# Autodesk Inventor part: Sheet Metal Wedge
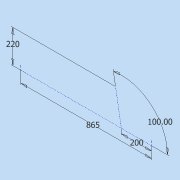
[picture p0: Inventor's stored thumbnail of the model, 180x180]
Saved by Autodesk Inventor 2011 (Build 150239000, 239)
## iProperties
Created: 2010-10
Part Number: Sheet Metal Wedge
Material: Default
Document SubType Name: Sheet Metal
Designer: jmather
Density: 1 g/cm^3
Sheet Metal Rule: Default_mm
Author: jmather
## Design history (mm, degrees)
sketch "Sketch1"
  geometry: L1 (-200, 0)-(665, 0); L2 (0, 0)-(38.792, 220)
  constraints: 4 end point, 1 horizontal, 1 point on line
  dimensions: "d3" = 865 distance of L1.start L1.end; "d4" = 200 distance of L2.start L1.start; "d15" = 100 deg angle of L1 L2; "d16" = 220 vertical distance of L1.end L2.end
workplane "Work Plane1"
sketch "Sketch2"
  geometry: L1 (0, 0)-(223.394, 0) reference; L2 (0, 0)-(223.394, -319.039); L3 (0, 0)-(223.394, 319.039); L4 (223.394, -319.039)-(223.394, 319.039)
  constraints: 6 end point, 1 midpoint, 1 perpendicular, 1 other
  dimensions: "d6" = 110 deg angle of L3 L2
feature "Stitch Surface1"
workplane "Work Plane2"
sketch "Sketch3"
  geometry: L1 (0, 0)-(-455.201, 0) reference; L2 (-455.201, 0)-(-223.607, -227.565); L3 (0, 0)-(-447.214, -455.131); L4 (0, 0)-(0, -218); L5 (-455.058, 0)-(-223.537, -227.494); L6 (-455.198, -0.143)-(-223.677, -227.637); L7 (-223.607, -227.565)-(-4.403, -442.957); L8 (-223.537, -227.494)-(-164.822, -285.188); L9 (0, 0)-(-455.058, 0); L10 (-447.214, -455.131)-(-229.248, -451.306); L11 (-447.214, -455.131)-(-455.198, -0.143); L12 (-164.962, -285.331)-(-455.198, -0.143); A1 r 225 centre (-4.403, -442.957) between (0, -218) and (-164.822, -285.188); A2 r 225 centre (-4.403, -442.957) between (-164.962, -285.331) and (-229.248, -451.306); 1 further point
  constraints: 22 end point, 4 perpendicular, 4 point on circle, 4 symmetric about line, 3 parallel, 3 point on line, 2 centre point, 1 coincident, 1 midpoint, 1 other
  dimensions: "d19" = 0.2 distance between parallel lines of L6 L5; "d20" = 218 distance of L1.start L4.end; "d21" = 225 radius of A1
workplane "Work Plane3"
sketch "Sketch4"
  geometry: L1 (-7.862, 0)-(-736.426, 0) reference; L2 (-736.426, 0)-(-604.436, 173.501) reference; L3 (-100, 0)-(-723.861, 0); L4 (-723.861, 0)-(-704.842, 25); L5 (-704.842, 25)-(-100, 25); L6 (-100, 0)-(-100, 25); 2 further points
  constraints: 8 end point, 2 parallel, 2 point on line, 1 perpendicular
  dimensions: "d27" = 25 distance of L3.start L5.end; "d29" = 10 distance between parallel lines of L2 L4; "d63" = 100 distance from line of L6 point (0, 0)
sketch "Sketch5"
  geometry: L1 (-736.426, 0)-(-604.436, 173.501) reference; L2 (-704.842, 25)-(-100, 25) reference; L3 (-613.518, 161.563)-(-593.621, 146.427); L4 (-593.621, 146.427)-(-685.235, 26); L5 (-685.235, 26)-(-716.646, 26); 1 further point
  constraints: 6 end point, 2 perpendicular, 2 point on line, 1 parallel
  dimensions: "d30" = 25 distance of L3.start L3.end (= d27); "d31" = 1 distance between parallel lines of L2 L5; "d32" = 15 distance from line of L3 L1.end
fillet "Fillet1" dims "d17" = 6 (= 2 x Thickness)
thicken "Thicken1" dims "d18" = 3 (= Thickness)
node "Face1"
node "Face4"
node "Face2"
node "Face3"
node "Flange1"
feature "Corner Chamfer1" dims "d55" = 19, "d56" = 6, angle "d57" = 45 deg
feature "Corner2" dims "d58" = 12 (= CornerReliefSize), "d59" = 3 (= BendRadius), "d60" = 0.2, "d61" = 0, "d62" = 10, "Thickness" = 3 (derived)
mirror "Mirror1"
body "Solid1"
body "Srf1"
body "Srf2"
body "Srf3"
face "Plate1" dims "d22" = 3 (= BendRadius), "d23" = 3 (= BendReliefWidth), "d25" = 6 (= MinimumRemnant), "Thickness" = 3 (derived)
bend "Bend1" dims "d22" = 3 (= BendRadius), "d23" = 3 (= BendReliefWidth), "d24" = 1.5 (= BendReliefDepth), "d25" = 6 (= MinimumRemnant), "d26" = 3 (= BendRadius), "SeamGap" = 0.01, "Thickness" = 3 (derived)
face "Plate2" dims "d33" = 3 (= BendRadius), "d34" = 3 (= BendReliefWidth), "d36" = 6 (= MinimumRemnant), "Thickness" = 3 (derived)
bend "Bend2" dims "d33" = 3 (= BendRadius), "d34" = 3 (= BendReliefWidth), "d35" = 1.5 (= BendReliefDepth), "d36" = 6 (= MinimumRemnant), "d37" = 3 (= BendRadius), "SeamGap" = 0.01, "Thickness" = 3 (derived)
face "Plate3" dims "d38" = 3 (= BendRadius), "d39" = 3 (= BendReliefWidth), "d41" = 6 (= MinimumRemnant), "Thickness" = 3 (derived)
bend "Bend3" dims "d38" = 3 (= BendRadius), "d39" = 3 (= BendReliefWidth), "d40" = 1.5 (= BendReliefDepth), "d41" = 6 (= MinimumRemnant), "d42" = 3 (= BendRadius), "SeamGap" = 0.01, "Thickness" = 3 (derived)
sketch "Sketch6"
  geometry: L1 (-270.377, -249.1)-(-16.18, -14.907); L2 (-16.18, -14.907)-(-33.119, 3.48); L3 (-33.119, 3.48)-(-287.317, -230.713); L4 (-287.317, -230.713)-(-270.377, -249.1)
  constraints: 8 end point
face "Plate4" dims "d43" = 3 (= BendReliefWidth), "d44" = 1.5 (= BendReliefDepth), "d45" = 6 (= MinimumRemnant), "d46" = 3 (= BendRadius), "d47" = 22, "d48" = 22, "d49" = 25, "d50" = 90 deg, "d51" = 3 (= BendRadius), "d52" = 12 (= CornerReliefSize), "d53" = 3 (= GapSize), "d54" = 3 (= JacobiRadiusSize), "SeamGap" = 0.01, "Thickness" = 3 (derived)
bend "Bend4" dims "d43" = 3 (= BendReliefWidth), "d44" = 1.5 (= BendReliefDepth), "d45" = 6 (= MinimumRemnant), "d46" = 3 (= BendRadius), "d49" = 25, "d50" = 90 deg, "d51" = 3 (= BendRadius), "SeamGap" = 0.01, "Thickness" = 3 (derived)
feature "Corner1" dims "d49" = 25, "d50" = 90 deg, "d52" = 12 (= CornerReliefSize), "d53" = 3 (= GapSize), "d54" = 3 (= JacobiRadiusSize)
face "Plate5" dims "d64" = 3 (= BendRadius), "d65" = 3 (= BendReliefWidth), "d67" = 6 (= MinimumRemnant), "Thickness" = 3 (derived)
bend "Bend5" dims "d64" = 3 (= BendRadius), "d65" = 3 (= BendReliefWidth), "d66" = 1.5 (= BendReliefDepth), "d67" = 6 (= MinimumRemnant), "d68" = 3 (= BendRadius), "SeamGap" = 0.01, "Thickness" = 3 (derived)
feature "LoftSrf1" dims "d7" = 0, "d8" = 90 deg, "d9" = 0, "d10" = 90 deg
feature "LoftSrf2" dims "d11" = 0, "d12" = 90 deg, "d13" = 0, "d14" = 90 deg
other parameters: "BendRadius" = 3 (= Thickness), "BendReliefWidth" = 3 (= Thickness), "BendReliefDepth" = 1.5 (= 0.5 x Thickness), "CornerReliefSize" = 12 (= 4 x Thickness), "MinimumRemnant" = 6 (= 2 x Thickness), "TransitionRadius" = 3 (= BendRadius), "JacobiRadiusSize" = 3 (= BendRadius), "GapSize" = 3 (= Thickness), "d5" = 90 deg
